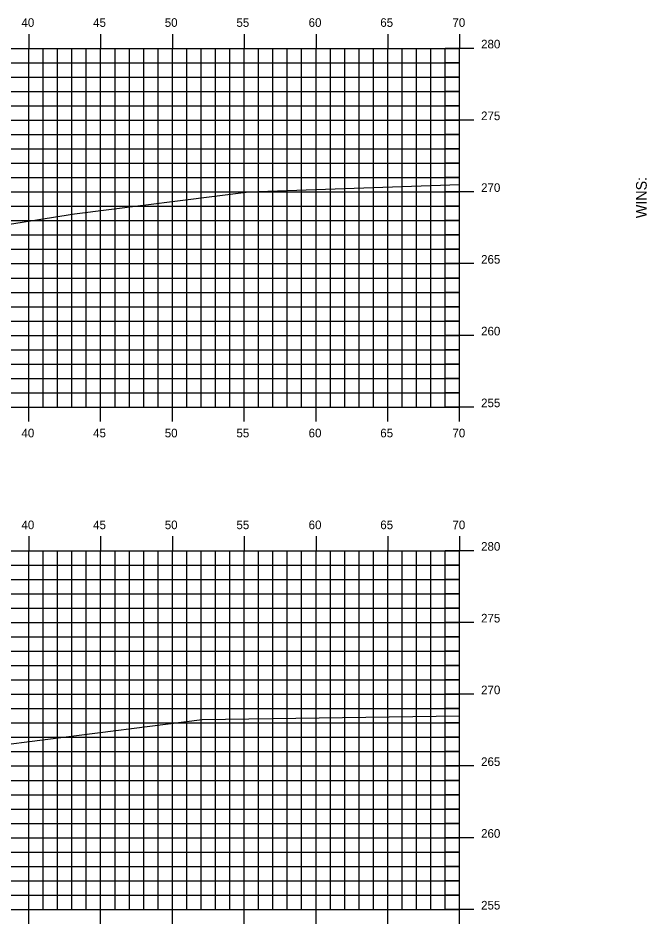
# Model space of a CAD drawing. Extents: x 1170543 to 1177585, y 609599 to 610623.
# Drawn here: x 1176653.2 to 1176696.9, y 610306.8 to 610369.9 of the extents above; entities that cross this region are included whole.
import ezdxf

# ---------------------------------------------------------------- set-up
doc = ezdxf.new("R2010")
doc.units = 0
for name, color, linetype in [('BORDER', 7, 'Continuous'), ('H_V ANNOTATION', 7, 'Continuous'), ('MAJOR', 7, 'Continuous'), ('MINOR', 7, 'Continuous'), ('S_Roadway_Centerline', 7, 'Continuous')]:
    doc.layers.add(name, color=color, linetype=linetype)

msp = doc.modelspace()

# ---------------------------------------------------------------- linework, layer by layer
at = {"layer": 'MAJOR'}
for p, q in [((1176653.898, 610368.803), (1176653.898, 610367.801)), ((1176658.898, 610368.803), (1176658.898, 610367.801)), ((1176663.898, 610368.803), (1176663.898, 610367.801)), ((1176668.898, 610368.803), (1176668.898, 610367.801)), ((1176673.898, 610368.803), (1176673.898, 610367.801)), ((1176678.898, 610368.803), (1176678.898, 610367.801)), ((1176683.898, 610368.803), (1176683.898, 610367.801)), ((1176543.898, 610367.801), (1176683.898, 610367.801)), ((1176543.898, 610367.801), (1176683.898, 610367.801)), ((1176653.898, 610342.801), (1176653.898, 610367.801)), ((1176658.898, 610342.801), (1176658.898, 610367.801)), ((1176663.898, 610342.801), (1176663.898, 610367.801)), ((1176668.898, 610342.801), (1176668.898, 610367.801)), ((1176673.898, 610342.801), (1176673.898, 610367.801)), ((1176678.898, 610342.801), (1176678.898, 610367.801)), ((1176684.9, 610367.801), (1176682.896, 610367.801)), ((1176683.898, 610342.801), (1176683.898, 610367.801)), ((1176683.898, 610342.801), (1176683.898, 610367.801)), ((1176543.898, 610362.801), (1176683.898, 610362.801)), ((1176684.9, 610362.801), (1176682.896, 610362.801)), ((1176543.898, 610357.801), (1176683.898, 610357.801)), ((1176684.9, 610357.801), (1176682.896, 610357.801)), ((1176543.898, 610352.801), (1176683.898, 610352.801)), ((1176684.9, 610352.801), (1176682.896, 610352.801)), ((1176543.898, 610347.801), (1176683.898, 610347.801)), ((1176684.9, 610347.801), (1176682.896, 610347.801)), ((1176543.898, 610342.801), (1176683.898, 610342.801)), ((1176543.898, 610342.801), (1176683.898, 610342.801)), ((1176653.898, 610341.799), (1176653.898, 610342.801)), ((1176658.898, 610341.799), (1176658.898, 610342.801)), ((1176663.898, 610341.799), (1176663.898, 610342.801)), ((1176668.898, 610341.799), (1176668.898, 610342.801)), ((1176673.898, 610341.799), (1176673.898, 610342.801)), ((1176678.898, 610341.799), (1176678.898, 610342.801)), ((1176684.9, 610342.801), (1176682.896, 610342.801)), ((1176683.898, 610341.799), (1176683.898, 610342.801)), ((1176653.898, 610333.803), (1176653.898, 610332.801)), ((1176658.898, 610333.803), (1176658.898, 610332.801)), ((1176663.898, 610333.803), (1176663.898, 610332.801)), ((1176668.898, 610333.803), (1176668.898, 610332.801)), ((1176673.898, 610333.803), (1176673.898, 610332.801)), ((1176678.898, 610333.803), (1176678.898, 610332.801)), ((1176683.898, 610333.803), (1176683.898, 610332.801)), ((1176543.898, 610332.801), (1176683.898, 610332.801)), ((1176543.898, 610332.801), (1176683.898, 610332.801)), ((1176653.898, 610307.801), (1176653.898, 610332.801)), ((1176658.898, 610307.801), (1176658.898, 610332.801)), ((1176663.898, 610307.801), (1176663.898, 610332.801)), ((1176668.898, 610307.801), (1176668.898, 610332.801)), ((1176673.898, 610307.801), (1176673.898, 610332.801)), ((1176678.898, 610307.801), (1176678.898, 610332.801)), ((1176684.9, 610332.801), (1176682.896, 610332.801)), ((1176683.898, 610307.801), (1176683.898, 610332.801)), ((1176683.898, 610307.801), (1176683.898, 610332.801)), ((1176543.898, 610327.801), (1176683.898, 610327.801)), ((1176684.9, 610327.801), (1176682.896, 610327.801)), ((1176543.898, 610322.801), (1176683.898, 610322.801)), ((1176684.9, 610322.801), (1176682.896, 610322.801)), ((1176543.898, 610317.801), (1176683.898, 610317.801)), ((1176684.9, 610317.801), (1176682.896, 610317.801)), ((1176543.898, 610312.801), (1176683.898, 610312.801)), ((1176684.9, 610312.801), (1176682.896, 610312.801)), ((1176543.898, 610307.801), (1176683.898, 610307.801)), ((1176543.898, 610307.801), (1176683.898, 610307.801)), ((1176653.898, 610306.799), (1176653.898, 610307.801)), ((1176658.898, 610306.799), (1176658.898, 610307.801)), ((1176663.898, 610306.799), (1176663.898, 610307.801)), ((1176668.898, 610306.799), (1176668.898, 610307.801)), ((1176673.898, 610306.799), (1176673.898, 610307.801)), ((1176678.898, 610306.799), (1176678.898, 610307.801)), ((1176684.9, 610307.801), (1176682.896, 610307.801)), ((1176683.898, 610306.799), (1176683.898, 610307.801))]:
    msp.add_line(p, q, dxfattribs=at)
at = {"layer": 'MINOR'}
for p, q in [((1176654.898, 610342.801), (1176654.898, 610367.801)), ((1176655.898, 610342.801), (1176655.898, 610367.801)), ((1176656.898, 610342.801), (1176656.898, 610367.801)), ((1176657.898, 610342.801), (1176657.898, 610367.801)), ((1176659.898, 610342.801), (1176659.898, 610367.801)), ((1176660.898, 610342.801), (1176660.898, 610367.801)), ((1176661.898, 610342.801), (1176661.898, 610367.801)), ((1176662.898, 610342.801), (1176662.898, 610367.801)), ((1176664.898, 610342.801), (1176664.898, 610367.801)), ((1176665.898, 610342.801), (1176665.898, 610367.801)), ((1176666.898, 610342.801), (1176666.898, 610367.801)), ((1176667.898, 610342.801), (1176667.898, 610367.801)), ((1176669.898, 610342.801), (1176669.898, 610367.801)), ((1176670.898, 610342.801), (1176670.898, 610367.801)), ((1176671.898, 610342.801), (1176671.898, 610367.801)), ((1176672.898, 610342.801), (1176672.898, 610367.801)), ((1176674.898, 610342.801), (1176674.898, 610367.801)), ((1176675.898, 610342.801), (1176675.898, 610367.801)), ((1176676.898, 610342.801), (1176676.898, 610367.801)), ((1176677.898, 610342.801), (1176677.898, 610367.801)), ((1176679.898, 610342.801), (1176679.898, 610367.801)), ((1176680.898, 610342.801), (1176680.898, 610367.801)), ((1176681.898, 610342.801), (1176681.898, 610367.801)), ((1176682.898, 610342.801), (1176682.898, 610367.801)), ((1176543.898, 610366.801), (1176683.898, 610366.801)), ((1176683.898, 610366.801), (1176682.896, 610366.801)), ((1176543.898, 610365.801), (1176683.898, 610365.801)), ((1176683.898, 610365.801), (1176682.896, 610365.801)), ((1176543.898, 610364.801), (1176683.898, 610364.801)), ((1176683.898, 610364.801), (1176682.896, 610364.801)), ((1176543.898, 610363.801), (1176683.898, 610363.801)), ((1176683.898, 610363.801), (1176682.896, 610363.801)), ((1176543.898, 610361.801), (1176683.898, 610361.801)), ((1176683.898, 610361.801), (1176682.896, 610361.801)), ((1176543.898, 610360.801), (1176683.898, 610360.801)), ((1176683.898, 610360.801), (1176682.896, 610360.801)), ((1176543.898, 610359.801), (1176683.898, 610359.801)), ((1176683.898, 610359.801), (1176682.896, 610359.801)), ((1176543.898, 610358.801), (1176683.898, 610358.801)), ((1176683.898, 610358.801), (1176682.896, 610358.801)), ((1176543.898, 610356.801), (1176683.898, 610356.801)), ((1176683.898, 610356.801), (1176682.896, 610356.801)), ((1176543.898, 610355.801), (1176683.898, 610355.801)), ((1176683.898, 610355.801), (1176682.896, 610355.801)), ((1176543.898, 610354.801), (1176683.898, 610354.801)), ((1176683.898, 610354.801), (1176682.896, 610354.801)), ((1176543.898, 610353.801), (1176683.898, 610353.801)), ((1176683.898, 610353.801), (1176682.896, 610353.801)), ((1176543.898, 610351.801), (1176683.898, 610351.801)), ((1176683.898, 610351.801), (1176682.896, 610351.801)), ((1176543.898, 610350.801), (1176683.898, 610350.801)), ((1176683.898, 610350.801), (1176682.896, 610350.801)), ((1176543.898, 610349.801), (1176683.898, 610349.801)), ((1176683.898, 610349.801), (1176682.896, 610349.801)), ((1176543.898, 610348.801), (1176683.898, 610348.801)), ((1176683.898, 610348.801), (1176682.896, 610348.801)), ((1176543.898, 610346.801), (1176683.898, 610346.801)), ((1176683.898, 610346.801), (1176682.896, 610346.801)), ((1176543.898, 610345.801), (1176683.898, 610345.801)), ((1176683.898, 610345.801), (1176682.896, 610345.801)), ((1176543.898, 610344.801), (1176683.898, 610344.801)), ((1176683.898, 610344.801), (1176682.896, 610344.801)), ((1176543.898, 610343.801), (1176683.898, 610343.801)), ((1176683.898, 610343.801), (1176682.896, 610343.801)), ((1176654.898, 610307.801), (1176654.898, 610332.801)), ((1176655.898, 610307.801), (1176655.898, 610332.801)), ((1176656.898, 610307.801), (1176656.898, 610332.801)), ((1176657.898, 610307.801), (1176657.898, 610332.801)), ((1176659.898, 610307.801), (1176659.898, 610332.801)), ((1176660.898, 610307.801), (1176660.898, 610332.801)), ((1176661.898, 610307.801), (1176661.898, 610332.801)), ((1176662.898, 610307.801), (1176662.898, 610332.801)), ((1176664.898, 610307.801), (1176664.898, 610332.801)), ((1176665.898, 610307.801), (1176665.898, 610332.801)), ((1176666.898, 610307.801), (1176666.898, 610332.801)), ((1176667.898, 610307.801), (1176667.898, 610332.801)), ((1176669.898, 610307.801), (1176669.898, 610332.801)), ((1176670.898, 610307.801), (1176670.898, 610332.801)), ((1176671.898, 610307.801), (1176671.898, 610332.801)), ((1176672.898, 610307.801), (1176672.898, 610332.801)), ((1176674.898, 610307.801), (1176674.898, 610332.801)), ((1176675.898, 610307.801), (1176675.898, 610332.801)), ((1176676.898, 610307.801), (1176676.898, 610332.801)), ((1176677.898, 610307.801), (1176677.898, 610332.801)), ((1176679.898, 610307.801), (1176679.898, 610332.801)), ((1176680.898, 610307.801), (1176680.898, 610332.801)), ((1176681.898, 610307.801), (1176681.898, 610332.801)), ((1176682.898, 610307.801), (1176682.898, 610332.801)), ((1176543.898, 610331.801), (1176683.898, 610331.801)), ((1176683.898, 610331.801), (1176682.896, 610331.801)), ((1176543.898, 610330.801), (1176683.898, 610330.801)), ((1176683.898, 610330.801), (1176682.896, 610330.801)), ((1176543.898, 610329.801), (1176683.898, 610329.801)), ((1176683.898, 610329.801), (1176682.896, 610329.801)), ((1176543.898, 610328.801), (1176683.898, 610328.801)), ((1176683.898, 610328.801), (1176682.896, 610328.801)), ((1176543.898, 610326.801), (1176683.898, 610326.801)), ((1176683.898, 610326.801), (1176682.896, 610326.801)), ((1176543.898, 610325.801), (1176683.898, 610325.801)), ((1176683.898, 610325.801), (1176682.896, 610325.801)), ((1176543.898, 610324.801), (1176683.898, 610324.801)), ((1176683.898, 610324.801), (1176682.896, 610324.801)), ((1176543.898, 610323.801), (1176683.898, 610323.801)), ((1176683.898, 610323.801), (1176682.896, 610323.801)), ((1176543.898, 610321.801), (1176683.898, 610321.801)), ((1176683.898, 610321.801), (1176682.896, 610321.801)), ((1176543.898, 610320.801), (1176683.898, 610320.801)), ((1176683.898, 610320.801), (1176682.896, 610320.801)), ((1176543.898, 610319.801), (1176683.898, 610319.801)), ((1176683.898, 610319.801), (1176682.896, 610319.801)), ((1176543.898, 610318.801), (1176683.898, 610318.801)), ((1176683.898, 610318.801), (1176682.896, 610318.801)), ((1176543.898, 610316.801), (1176683.898, 610316.801)), ((1176683.898, 610316.801), (1176682.896, 610316.801)), ((1176543.898, 610315.801), (1176683.898, 610315.801)), ((1176683.898, 610315.801), (1176682.896, 610315.801)), ((1176543.898, 610314.801), (1176683.898, 610314.801)), ((1176683.898, 610314.801), (1176682.896, 610314.801)), ((1176543.898, 610313.801), (1176683.898, 610313.801)), ((1176683.898, 610313.801), (1176682.896, 610313.801)), ((1176543.898, 610311.801), (1176683.898, 610311.801)), ((1176683.898, 610311.801), (1176682.896, 610311.801)), ((1176543.898, 610310.801), (1176683.898, 610310.801)), ((1176683.898, 610310.801), (1176682.896, 610310.801)), ((1176543.898, 610309.801), (1176683.898, 610309.801)), ((1176683.898, 610309.801), (1176682.896, 610309.801)), ((1176543.898, 610308.801), (1176683.898, 610308.801)), ((1176683.898, 610308.801), (1176682.896, 610308.801))]:
    msp.add_line(p, q, dxfattribs=at)
at = {"layer": 'S_Roadway_Centerline'}
for points in [[(1176609.213, 610358.637), (1176611.353, 610358.595), (1176614.219, 610358.54), (1176616.12, 610358.493), (1176619.225, 610358.416), (1176620.888, 610358.366), (1176624.232, 610358.264), (1176626.807, 610358.162), (1176626.995, 610358.155), (1176627.057, 610358.152), (1176627.583, 610358.076), (1176628.422, 610357.955), (1176633.893, 610356.932), (1176645.24, 610354.395), (1176657.074, 610356.27), (1176669.21, 610357.804), (1176683.898, 610358.317)], [(1176608.648, 610322.928), (1176611.394, 610322.872), (1176613.364, 610322.823), (1176616.403, 610322.744), (1176618.08, 610322.696), (1176621.413, 610322.599), (1176623.833, 610322.495), (1176624.081, 610322.485), (1176624.164, 610322.481), (1176624.743, 610322.34), (1176625.747, 610322.169), (1176633.83, 610320.308), (1176641.95, 610318.407), (1176651.361, 610319.183), (1176665.979, 610321.032), (1176683.898, 610321.302)]]:
    msp.add_lwpolyline(points, dxfattribs=at)

# ---------------------------------------------------------------- texts
at = {"layer": 'BORDER'}
msp.add_text('WINS:', height=0.7453, rotation=90, dxfattribs=at).set_placement((1176696.933, 610355.969))
at = {"layer": 'H_V ANNOTATION'}
for s, p in [('40', (1176653.384, 610369.301)), ('50', (1176663.363, 610369.301)), ('60', (1176673.384, 610369.301)), ('65', (1176678.376, 610369.301)), ('70', (1176683.4, 610369.301)), ('45', (1176658.376, 610369.301)), ('55', (1176668.355, 610369.301)), ('280', (1176685.398, 610367.801)), ('275', (1176685.398, 610362.801)), ('270', (1176685.398, 610357.801)), ('265', (1176685.398, 610352.801)), ('260', (1176685.398, 610347.801)), ('255', (1176685.398, 610342.801)), ('40', (1176653.384, 610340.701)), ('45', (1176658.376, 610340.701)), ('50', (1176663.363, 610340.701)), ('55', (1176668.355, 610340.701)), ('60', (1176673.384, 610340.701)), ('65', (1176678.376, 610340.701)), ('70', (1176683.4, 610340.701)), ('40', (1176653.384, 610334.301)), ('45', (1176658.376, 610334.301)), ('50', (1176663.363, 610334.301)), ('55', (1176668.355, 610334.301)), ('60', (1176673.384, 610334.301)), ('65', (1176678.376, 610334.301)), ('70', (1176683.4, 610334.301)), ('280', (1176685.398, 610332.801)), ('275', (1176685.398, 610327.801)), ('270', (1176685.398, 610322.801)), ('265', (1176685.398, 610317.801)), ('260', (1176685.398, 610312.801)), ('255', (1176685.398, 610307.801))]:
    msp.add_text(s, height=0.6, dxfattribs=at).set_placement(p)

doc.saveas('drawing.dxf')
